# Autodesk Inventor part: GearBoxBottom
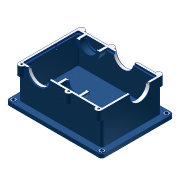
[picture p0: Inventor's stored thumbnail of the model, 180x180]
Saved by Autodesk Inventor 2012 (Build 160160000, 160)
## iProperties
Part Number: GearBoxBottom
Document SubType Name: Modeling
Created: 2003-11
Designer: ales
Manufacturer: Standard
Standards Organization: Custom
Density: 1 g/cm^3
Material: Default
Control State: 0
Master: False
Checked Out: False
Shininess: 64.0
Length Units: 11269
Angle Units: 11279
Time Units: 11290
Mass Units: 11283
Length Display Precision: 3
Angle Display Precision: 2
Compacted: True
Density: 0.0
Volumn: 0.0
Area: 0.0
PropertySet Name: Model Information
Author: ales
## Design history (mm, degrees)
sketch "Sketch1"
  geometry: L1 (0, 0)-(230, 0); L2 (230, 0)-(230, 165); L3 (230, 165)-(0, 165); L4 (0, 165)-(0, 0)
  constraints: 8 end point, 2 parallel, 1 horizontal, 1 perpendicular, 1 other
  dimensions: "d0" = 165 distance of L3.end L1.start; "d1" = 230 distance of L1.start L1.end
extrude "Main Body" new body sketch "Sketch1" distance "d2" = 90; taper "d3" = 0 deg
shell "Shell1" dims "d4" = 10
sketch "Sketch26"
  geometry: L1 (150.022, -20.005)-(155.022, -20.005); L2 (155.022, -20.005)-(155.022, -30.005); L3 (155.022, -30.005)-(159.525, -30.005); L4 (159.525, -30.005)-(152.522, -37.008); L5 (152.522, -37.008)-(145.518, -30.005); L6 (145.518, -30.005)-(150.022, -30.005); L7 (150.022, -30.005)-(150.022, -20.005)
  constraints: 14 end point, 3 parallel, 2 equal length, 2 perpendicular, 1 horizontal, 1 point on line
  dimensions: "d130" = 5 distance of L1.start L1.end; "d131" = 10 distance of L1.end L2.end
extrude "Arrow" join sketch "Sketch26" distance "d132" = 1; taper "d133" = 0 deg
sketch "Sketch17" dims "d86" = 17
  geometry: L1 (230, 0)-(0, 0) reference; L2 (0, 165)-(230, 165) reference; C1 r 8.5 at (91.5, 165); C2 r 8.5 at (138.5, 0); 4 further points
  constraints: 6 point on line, 4 horizontal alignment, 2 centre point, 10 other
  dimensions: "d91" = 130 distance of C1.centre point (221.5, 165); "d92" = 130 distance of C2.centre point (8.5, 0)
extrude "Extrusion15" join sketch "Sketch17" distance "d87" = 25; taper "d88" = 0 deg
sketch "Sketch14"
  geometry: L1 (220, 10)-(10, 10) reference; L2 (10, 10)-(10, 155) reference; L3 (10, 155)-(220, 155) reference; L4 (220, 155)-(220, 10) reference; L5 (6, 6)-(224, 6); L6 (224, 6)-(224, 159); L7 (224, 159)-(6, 159); L8 (6, 159)-(6, 6)
  constraints: 8 end point, 3 other
  dimensions: "d74" = 4 distance between parallel lines of L1 L5
extrude "Extrusion13" cut sketch "Sketch14" distance "d75" = 5; taper "d76" = 0 deg
sketch "Sketch3"
  geometry: L1 (210, 0)-(0, 0) reference; L2 (0, 80)-(0, 0) reference; C1 r 30 at (45, 0)
  constraints: 1 centre point, 1 point on line
  dimensions: "d7" = 60 diameter of C1; "d13" = 45 distance from line of L2 C1.centre
extrude "Extrusion3" cut sketch "Sketch3" stored distance "d8" = 90; taper "d9" = 0 deg
sketch "Sketch4"
  geometry: L1 (0, 0)-(210, 0) reference; C1 r 27.5 at (125, 0); 1 further point
  constraints: 1 centre point, 1 point on line
  dimensions: "d10" = 55 diameter of C1; "d14" = 80 distance of C1.centre point (45, 0)
extrude "Extrusion4" cut sketch "Sketch4" stored distance "d11" = 90; taper "d12" = 0 deg
workaxis "Work Axis2"
sketch "Sketch33"
  geometry: L1 (80, -66.8)-(80, 211.8) reference; C1 r 27.5 at (80, 95.251); 1 further point
  constraints: 1 centre point, 1 point on line
  dimensions: "d180" = 55 diameter of C1; "d181" = 50 distance of point (75, 145) C1.centre
extrude "Bearing Holder Output Bevel" cut sketch "Sketch33" stored distance "d182" = 10; taper "d183" = 0 deg
node "Bearing Holder Output Bevel Work Plane"
  workaxis "Work Axis1"
sketch "Sketch5"
  geometry: L1 (0, 0)-(-230, 0) reference; L2 (0, 165)-(0, 0) reference; L3 (-230, 165)-(0, 165) reference; L4 (-230, 0)-(-230, 165) reference; L5 (17, -17)-(-247, -17); L6 (-247, -17)-(-247, 182); L7 (-247, 182)-(17, 182); L8 (17, 182)-(17, -17)
  constraints: 8 end point, 2 parallel, 1 horizontal, 1 perpendicular
  dimensions: "d15" = 17 distance between parallel lines of L8 L2; "d16" = 17 distance between parallel lines of L3 L7 (= d15); "d17" = 17 distance between parallel lines of L6 L4 (= d15); "d18" = 17 distance between parallel lines of L5 L1 (= d15)
extrude "Extrusion5" join sketch "Sketch5" distance "d19" = 10; taper "d20" = 0 deg
sketch "Sketch6"
  geometry: L1 (-17, -17)-(247, -17) reference; L2 (247, -17)-(247, 182) reference; L3 (247, 182)-(-17, 182) reference; L4 (-17, 182)-(-17, -17) reference; C1 r 6.5 at (-7, -7); C2 r 6.5 at (-7, 172); C3 r 6.5 at (237, -7); C4 r 6.5 at (237, 172)
  constraints: 4 centre point, 3 equal radius, 2 horizontal alignment, 2 vertical alignment
  dimensions: "d21" = 13 diameter of C1; "d22" = 10 distance from line of L4 C2.centre; "d23" = 10 distance from line of L3 C2.centre; "d24" = 10 distance from line of L2 C4.centre; "d25" = 10 distance from line of L1 C3.centre
extrude "Extrusion6" join sketch "Sketch6" distance "d26" = 1; taper "d27" = 0 deg
sketch "Sketch7"
  geometry: L1 (17, -17)-(-247, -17) reference; L2 (17, 182)-(17, -17) reference; L3 (-247, 182)-(17, 182) reference; L4 (-8, 8)-(-222, 8); L5 (-222, 8)-(-222, 157); L6 (-222, 157)-(-8, 157); L7 (-8, 157)-(-8, 8); L8 (-247, -17)-(-247, 182) reference
  constraints: 8 end point, 2 parallel, 1 horizontal, 1 perpendicular
  dimensions: "d33" = 25 distance between parallel lines of L1 L4; "d34" = 25 distance between parallel lines of L2 L7; "d35" = 25 distance between parallel lines of L3 L6; "d36" = 25 distance between parallel lines of L8 L5
extrude "Extrusion7" cut sketch "Sketch7" distance "d37" = 3; taper "d38" = 0 deg
sketch "Sketch15"
  geometry: C1 r 6.5 at (0, 0) reference
hole "Hole2" sketch "Sketch15" at (0, 0) diameter "d77" = 8.4; stored, may be unused: countersink angle "d81" = 82 deg, drill point angle "d83" = 118 deg; dims "d78" = 6, "d79" = 4, "d80" = 2, "d82" = 8
pattern_linear "Rectangular Pattern1" dims "d67" = 179 (= d0 + 2 x d15 - 2 x d23), "d70" = 244 (= d1 + 2 x d15 - 2 x d23)
sketch "Sketch18" dims "d97" = 52
  geometry: L1 (210, 75)-(152.042, 75) reference; L2 (12, 80)-(19, 80); L3 (71, 80)-(78, 80); A1 r 30 centre (45, 80) between (15, 80) and (75, 80) reference; A2 r 33 centre (45, 80) between (12, 80) and (78, 80); 3 further points
  constraints: 4 end point, 2 point on circle, 2 point on line, 1 centre point, 1 coincident, 1 collinear, 1 parallel, 4 other
  dimensions: "d135" = 7 dimension on A2
extrude "Bearing Holder Output" join sketch "Sketch18" distance "d100" = 15; taper "d101" = 0 deg
sketch "Sketch19"
  geometry: L1 (78, -80)-(71, -80) reference; L2 (77.619, -75)-(70.515, -75) reference; L3 (-4, -80)-(97.5, -80) reference; L4 (19, -80)-(12, -80) reference; L5 (19.485, -75)-(12.381, -75) reference; A1 r 33 centre (45, -80) between (78, -80) and (77.619, -75) reference; A2 r 26 centre (45, -80) between (71, -80) and (70.515, -75) reference; A3 r 26 centre (45, -80) between (19.485, -75) and (19, -80) reference; A4 r 33 centre (45, -80) between (12.381, -75) and (12, -80) reference
extrude "Extrusion18" join sketch "Sketch19" stored distance "d102" = 20; taper "d103" = 0 deg
sketch "Sketch20" dims "d107" = 52
  geometry: L1 (0, 0)-(0, -75) reference; L2 (158, -80)-(151, -80); L3 (99, -80)-(92, -80); A1 r 27.5 centre (125, -80) between (152.5, -80) and (97.5, -80) reference; A2 r 33 centre (125, -80) between (158, -80) and (92, -80); 3 further points
  constraints: 4 end point, 2 coincident, 2 point on circle, 2 point on line, 1 centre point, 1 collinear, 1 perpendicular, 4 other
  dimensions: "d134" = 7 dimension on A2
extrude "Bearing Holder Input" join sketch "Sketch20" distance "d110" = 15; taper "d111" = 0 deg
sketch "Sketch21"
  geometry: L1 (92.381, 75)-(99.485, 75) reference; L2 (99, 80)-(92, 80) reference; L3 (158, 80)-(151, 80) reference; L4 (150.515, 75)-(157.619, 75) reference; A1 r 33 centre (125, 80) between (92, 80) and (92.381, 75) reference; A2 r 26 centre (125, 80) between (99, 80) and (99.485, 75) reference; A3 r 26 centre (125, 80) between (150.515, 75) and (151, 80) reference; A4 r 33 centre (125, 80) between (157.619, 75) and (158, 80) reference
extrude "Extrusion20" join sketch "Sketch21" stored distance "d113" = 20; taper "d114" = 0 deg
sketch "Sketch22"
  geometry: L1 (92, -80)-(102, -80); L2 (148, -80)-(158, -80); A1 r 26 centre (125, -80) between (151, -80) and (99, -80) reference; A2 r 33 centre (125, -80) between (158, -80) and (92, -80) reference; A3 r 23 centre (125, -80) between (148, -80) and (102, -80)
  constraints: 4 end point, 2 point on circle, 1 centre point, 1 collinear, 1 horizontal
  dimensions: "d129" = 3 radial gap between concentric circles of A1 A3
extrude "Extrusion21" join sketch "Sketch22" distance "d116" = 3; taper "d117" = 0 deg
sketch "Sketch23"
  geometry: L1 (12, 80)-(22, 80); L2 (68, 80)-(78, 80); A1 r 26 centre (45, 80) between (19, 80) and (71, 80) reference; A2 r 33 centre (45, 80) between (12, 80) and (78, 80) reference; A3 r 23 centre (45, 80) between (22, 80) and (68, 80)
  constraints: 4 end point, 2 point on circle, 1 centre point, 1 collinear, 1 horizontal
  dimensions: "d128" = 3 radial gap between concentric circles of A3 A1
extrude "Extrusion22" join sketch "Sketch23" distance "d119" = 3; taper "d120" = 0 deg
sketch "Sketch24"
  geometry: C1 r 23 at (0, 0); A1 r 26 centre (0, 0) between (-25.515, -5) and (25.515, -5) reference
  constraints: 1 centre point, 1 coincident
  dimensions: "d121" = 3 radial gap between concentric circles of A1 C1
extrude "Extrusion23" cut sketch "Sketch24" distance "d122" = 4; taper "d123" = 0 deg
sketch "Sketch25"
  geometry: C1 r 23 at (0, 0); A1 r 26 centre (0, 0) between (25.515, 5) and (-25.515, 5) reference
  constraints: 1 centre point, 1 coincident
  dimensions: "d124" = 3 radial gap between concentric circles of A1 C1
extrude "Extrusion24" cut sketch "Sketch25" distance "d125" = 4; taper "d126" = 0 deg
fillet "Fillet1" dims "d28" = 7, "d29" = 3
fillet "Fillet2" dims "d30" = 2
fillet "Fillet3" dims "d31" = 8
fillet "Fillet4" dims "d32" = 1 (= d26)
fillet "Fillet5" dims "d39" = 5
fillet "Fillet6" dims "d40" = 2 (computed from d37)
fillet "Fillet8" dims "d89" = 2
fillet "Fillet9" dims "d90" = 2
chamfer "Chamfer1" distance "d42" = 1; stored, may be unused: second distance "d43" = 2, angle "d136" = 45 deg
chamfer "Chamfer2" distance "d93" = 2; stored, may be unused: second distance "d94" = 2, angle "d137" = 45 deg
fillet "Fillet11" dims "d127" = 2
sketch "Sketch27"
  geometry: 1 further point
hole "Hole3" sketch "Sketch27" at (8.5, 0) diameter "d138" = 4.917; stored, may be unused: countersink angle "d142" = 90 deg, drill point angle "d144" = 120 deg; dims "d139" = 7.2, "d140" = 4, "d141" = 2, "d143" = 12.3
sketch "Sketch28"
  geometry: 1 further point
hole "Hole4" sketch "Sketch28" at (8.5, 95) diameter "d145" = 4.917; stored, may be unused: countersink angle "d149" = 90 deg, drill point angle "d151" = 120 deg; dims "d146" = 7.2, "d147" = 4, "d148" = 2, "d150" = 12.3
sketch "Sketch31"
  geometry: 1 further point
hole "Hole7" sketch "Sketch31" at (221.5, 0) diameter "d166" = 4.917; stored, may be unused: countersink angle "d170" = 90 deg, drill point angle "d172" = 120 deg; dims "d167" = 7.2, "d168" = 4, "d169" = 2, "d171" = 12.3
sketch "Sketch32"
  geometry: 1 further point
hole "Hole8" sketch "Sketch32" at (138.5, 0) diameter "d173" = 4.917; stored, may be unused: countersink angle "d177" = 90 deg, drill point angle "d179" = 120 deg; dims "d174" = 7.2, "d175" = 4, "d176" = 2, "d178" = 12.3
body "Solid1"
other parameters: "d184" = 90 deg
